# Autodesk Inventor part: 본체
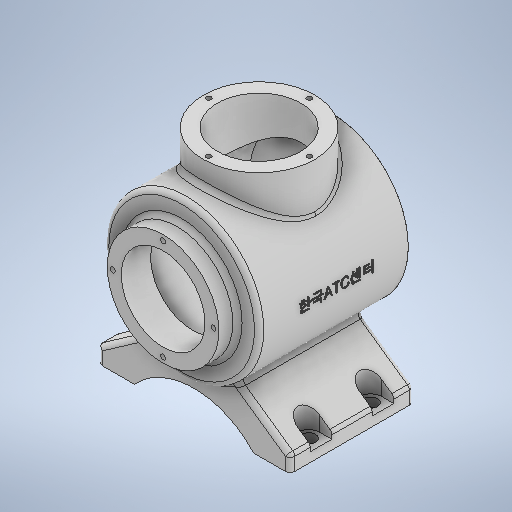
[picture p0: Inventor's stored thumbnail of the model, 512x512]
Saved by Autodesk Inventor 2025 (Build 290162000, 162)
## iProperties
Created: 2024-07
Part Number: 본체
Material: 일반
Document SubType Name: Modeling
Designer: SAMSUNG
Density: 1 g/cm^3
Appearance: 기본값
Author: SAMSUNG
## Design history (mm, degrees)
sketch "스케치1"
  geometry: C1 r 50 at (0, 0); C2 r 36 at (0, 0); 1 further point
  constraints: 2 centre point, 2 coincident
  dimensions: "d0" = 100 diameter of C1; "d3" = 72 diameter of C2
extrude "돌출7" new body sketch "스케치1" distance "d30" = 66; taper "d31" = 0 deg
sketch "스케치8"
  geometry: C1 r 36 at (0, 0); 1 further point
  constraints: 1 centre point, 1 coincident
  dimensions: "d32" = 72 diameter of C1
extrude "돌출8" join sketch "스케치8" distance "d33" = 12; taper "d34" = 0 deg
node "작업 평면4"
sketch "스케치10"
  geometry: L1 (-67, 58)-(-77, 58); L2 (-77, 58)-(-77, -22); L3 (-77, -22)-(-67, -22); L4 (-67, -22)-(-67, 58); L5 (36, 78)-(-36, 78) reference; 2 further points
  constraints: 8 end point, 2 parallel, 1 horizontal, 1 midpoint, 1 perpendicular
  dimensions: "d44" = 80 distance of L1.end L2.end; "d45" = 10 distance of L2.end L3.end; "d47" = 20 distance between parallel lines of L1 L5
extrude "돌출10" join sketch "스케치10" stored distance "d48" = 124; taper "d49" = 0 deg
sketch "스케치11"
  geometry: L1 (-28.488, -3.64)-(62, -67); L2 (16.364, -12.129)-(-62, -67); L3 (62, -77)-(62, -67) reference; L4 (-62, -67)-(-62, -77) reference; L5 (-62, -67)-(62, -67); 4 further points
  constraints: 6 end point, 2 coincident, 1 perpendicular
  dimensions: "d50" = 55 deg angle of L1 L3; "d51" = 55 deg angle of L2 L4
extrude "돌출11" join sketch "스케치11" stored distance "d52" = 60; taper "d53" = 0 deg
extrude "돌출12" join sketch "스케치11" stored distance "d54" = 10; taper "d55" = 0 deg
sketch "스케치12"
  geometry: L1 (0, 127.846)-(0, -126.764); L2 (36, 78)-(-36, 78) reference; L3 (50, 0)-(-42.278, 0) reference; L4 (50, 0)-(50, -77.532); L5 (-50, 58)-(-50, 66) reference; L6 (-50, 58)-(-50, -42); L7 (0, 0)-(0, -56.335); L8 (57.014, -30.336)-(0, -30.336); A1 r 113 centre (0, 71) between (0, -42) and (50, -30.336); 2 further points
  constraints: 10 end point, 8 point on line, 3 vertical, 2 point on circle, 1 centre point, 1 horizontal
  dimensions: "d87" = 113 radius of A1; "d88" = 120 distance from line of A1.start L2
sketch "스케치14"
  geometry: L1 (36, 78)-(-36, 78) reference; 1 further point
  dimensions: "d59" = 78 distance from line of L1 point (0, 0) (derived)
sketch "스케치15"
  geometry: L1 (62, 133.976)-(62, -44.154); L2 (23.5, 0)-(100.5, 0); L3 (124, 0)-(0, 0) reference; L4 (62, 0)-(62, 17); A1 r 52.096 centre (62, -35.096) between (100.5, 0) and (23.5, 0); 2 further points
  constraints: 6 end point, 3 midpoint, 3 point on circle, 3 point on line, 1 centre point, 1 horizontal, 1 vertical
  dimensions: "d65" = 77 distance of L2.end L2.start; "d66" = 17 distance of L4.start L4.end
extrude "돌출14" cut sketch "스케치15" extent not by distance; stored distance "d67" = 0; taper "d68" = 0 deg
node "작업 평면5"
sketch "스케치16"
  geometry: L1 (36, 78)-(-36, 78) reference; C1 r 36 at (0, 16); 2 further points
  constraints: 1 centre point, 1 midpoint, 1 vertical alignment
  dimensions: "d74" = 72 diameter of C1; "d75" = 62 distance from line of C1.centre L1
extrude "돌출15" join sketch "스케치16" stored distance "d76" = 10; taper "d77" = 0 deg
sketch "스케치17"
  geometry: C1 r 36 at (0, 0) reference; 2 further points
  constraints: 1 coincident
hole "구멍1" sketch "스케치17" at (0, 0) diameter "d78" = 54; stored, may be unused: countersink angle "d82" = 90 deg, drill point angle "d84" = 0 deg; dims "d79" = 8, "d80" = 4, "d81" = 2, "d83" = 19
extrude "돌출16" join sketch "스케치1" distance "d90" = 30.336; taper "d91" = 0 deg
revolve "회전2" stored, may be unused: angle "d92" = 90 deg
sketch "스케치19"
  geometry: L1 (43, 59)-(0, 59); L2 (0, 59)-(0, -21); L3 (0, -21)-(43, -21); L4 (43, -21)-(43, 59); L5 (0, 113.417)-(0, -94.649); L6 (27, 59)-(-27, 59) reference; 2 further points
  constraints: 10 end point, 3 point on line, 2 parallel, 1 horizontal, 1 midpoint, 1 perpendicular, 1 vertical
  dimensions: "d94" = 43 distance of L1.start L1.end; "d95" = 80 distance of L3.end L1.start
revolve "회전3" sketch "스케치19" stored, may be unused: angle "d96" = 90 deg
sketch "스케치20"
  geometry: C1 r 36 at (0, 0) reference; 2 further points
  constraints: 1 coincident
hole "구멍2" sketch "스케치20" at (0, 0) diameter "d97" = 54; stored, may be unused: countersink angle "d101" = 90 deg, drill point angle "d103" = 0 deg; dims "d98" = 6, "d99" = 4, "d100" = 2, "d102" = 50
sketch "스케치21" dims "d111" = 65
  geometry: C1 r 36 at (0, 0) reference; 3 further points
  constraints: 2 horizontal alignment, 1 vertical alignment, 3 other
hole "구멍3" sketch "스케치21" at (-32.5, 0) diameter "d104" = 3.242; stored, may be unused: countersink angle "d108" = 90 deg, drill point angle "d110" = 120 deg; dims "d105" = 8, "d106" = 4, "d107" = 2, "d109" = 10
sketch "스케치22" dims "d122" = 65
  geometry: 3 further points
  constraints: 2 vertical alignment, 1 coincident, 2 other
hole "구멍4" sketch "스케치22" at (0, 32.5) diameter "d115" = 3.242; stored, may be unused: countersink angle "d119" = 90 deg, drill point angle "d121" = 120 deg; dims "d116" = 8, "d117" = 4, "d118" = 2, "d120" = 10
node "작업 평면6"
sketch "스케치23"
  geometry: L1 (-62, -22)-(-26.694, -22) reference; L2 (-62, -22)-(-62, 58) reference; L3 (62, 58)-(62, -22) reference; L4 (26.694, -22)-(62, -22) reference; L5 (-54, -2)-(-70, -2); L6 (-54, 5)-(-70, 5); L7 (-70, -9)-(-54, -9); L8 (-54, 38)-(-70, 38); L9 (-54, 45)-(-70, 45); L10 (-70, 31)-(-54, 31); A1 r 7 centre (-54, -2) between (-54, -9) and (-54, 5); A2 r 7 centre (-70, -2) between (-70, 5) and (-70, -9); A3 r 7 centre (-54, 38) between (-54, 31) and (-54, 45); A4 r 7 centre (-70, 38) between (-70, 45) and (-70, 31); 3 further points
  constraints: 16 end point, 8 point on circle, 8 tangent, 4 centre point, 2 horizontal, 2 midpoint, 2 parallel, 2 point on line, 1 vertical alignment
  dimensions: "d128" = 7 radius of A1; "d129" = 20 vertical distance of L1.start L5.start; "d131" = 8 distance from line of L2 L5.start; "d132" = 7 radius of A3; "d133" = 40 distance of point (-62, -2) point (-62, 38)
node "작업 평면8"
extrude "돌출17" cut sketch "스케치23" stored distance "d135" = 10; taper "d136" = 0 deg
sketch "스케치24"
  geometry: A1 r 7 centre (0, -7) between (0, 0) and (0, -14) reference; A2 r 7 centre (0, 33) between (0, 40) and (0, 26) reference; 3 further points
  constraints: 2 coincident
hole "구멍5" sketch "스케치24" at (0, -7), (0, 33) diameter "d137" = 9; stored, may be unused: countersink angle "d141" = 90 deg, drill point angle "d143" = 0 deg; dims "d138" = 8, "d139" = 4, "d140" = 2, "d142" = 10
sketch "스케치25"
  geometry: A1 r 7 centre (8, 7) between (8, 0) and (8, 14) reference; A2 r 7 centre (8, 47) between (8, 40) and (8, 54) reference; 3 further points
  constraints: 2 coincident
hole "구멍6" sketch "스케치25" at (8, 7), (8, 47) diameter "d144" = 9; stored, may be unused: countersink angle "d148" = 90 deg, drill point angle "d150" = 0 deg; dims "d145" = 6, "d146" = 4, "d147" = 2, "d149" = 8
fillet "모깎기1" dims "d151" = 3
fillet "모깎기2" dims "d152" = 3
fillet "모깎기3" dims "d153" = 3
node "작업 평면9"
sketch "스케치26"
  geometry: L1 (36, 78)-(-36, 78) reference; 2 further points
  constraints: 1 other
  dimensions: "d155" = 62 distance from line of L1 point (0.835, 16)
feature "엠보싱1" sketch "스케치26" dims "d0" = 100, "d156" = 0.5, "d157" = 0
node "솔리드3"
pattern_circular "원형 패턴1" dims angle "d113" = 360 deg
pattern_circular "원형 패턴2" dims angle "d124" = 360 deg
mirror "미러1"
feature "A9D066F2-1C7D-4E18-AEED-F7BC21143FA4" dims "d78" = 54, "d79" = 8, "d80" = 4, "d81" = 2, "d82" = 90 deg, "d83" = 19, "d84" = 0
other parameters: "d10" = 0.5, "d11" = 2, "d12" = 0, "d35" = 65, "d73" = 65, "d127" = -40.25, "d154" = 95.75
